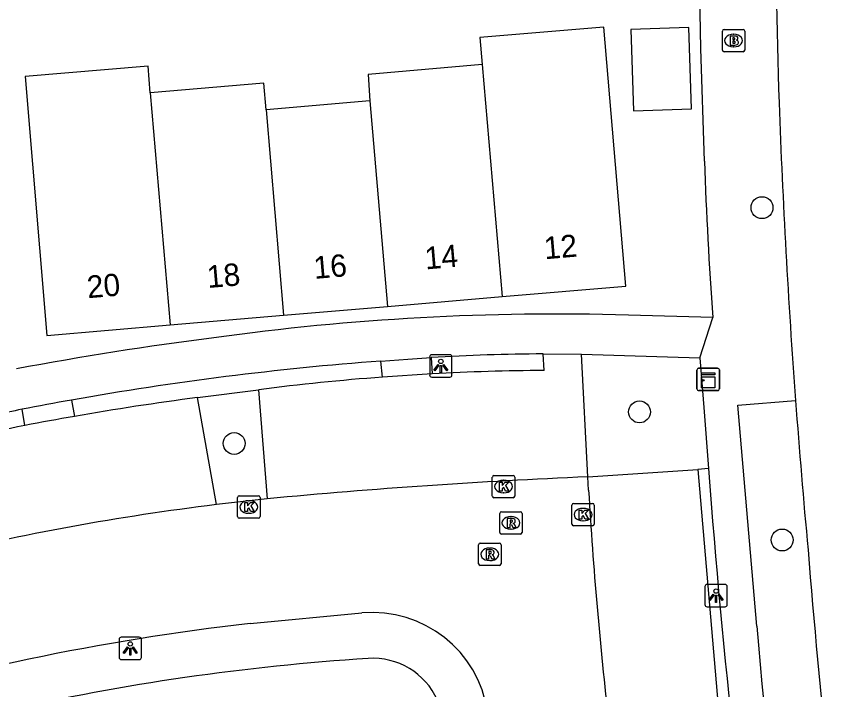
# Model space of a CAD drawing. Extents: x 160158 to 160921, y 381517 to 382041.
# Drawn here: x 160460.93 to 160497.47, y 381637.81 to 381667.92 of the extents above; entities that cross this region are included whole.
import ezdxf

# ---------------------------------------------------------------- set-up
doc = ezdxf.new("R2010")
doc.units = 0
for name, color, linetype in [('IMGEO_Boom', 7, 'Continuous'), ('IMGEO_Brandkraan', 7, 'Continuous'), ('IMGEO_Fietspad_gesloten', 7, 'Continuous'), ('IMGEO_Groenvoorziening', 7, 'Continuous'), ('IMGEO_Haag', 7, 'Continuous'), ('IMGEO_Kast', 7, 'Continuous'), ('IMGEO_Kolk', 7, 'Continuous'), ('IMGEO_Lichtpunt', 7, 'Continuous'), ('IMGEO_Pand', 7, 'Continuous'), ('IMGEO_Pand_nummerreeks', 7, 'Continuous'), ('IMGEO_Parkeervlak_open', 7, 'Continuous'), ('IMGEO_Rijbaan_lokaal_open', 7, 'Continuous'), ('IMGEO_Rioolput', 7, 'Continuous'), ('IMGEO_Voetpad_open', 7, 'Continuous')]:
    doc.layers.add(name, color=color, linetype=linetype)

msp = doc.modelspace()

# ---------------------------------------------------------------- linework, layer by layer
at = {"layer": 'IMGEO_Boom'}
for centre in [(160494.263, 381659.367), (160488.788, 381650.234), (160470.666, 381648.826), (160495.165, 381644.507)]:
    msp.add_circle(centre, 0.489, dxfattribs=at)
at = {"layer": 'IMGEO_Brandkraan'}
for p, q in [((160492.566, 381667.339), (160493.418, 381667.339)), ((160492.491, 381666.413), (160492.491, 381667.265)), ((160492.979, 381667.119), (160493.004, 381667.119)), ((160493.492, 381667.265), (160493.492, 381666.413)), ((160493.418, 381666.339), (160492.566, 381666.339)), ((160493.002, 381666.559), (160492.977, 381666.559))]:
    msp.add_line(p, q, dxfattribs=at)
for points in [[(160492.566, 381667.339), (160493.418, 381667.339)], [(160492.491, 381666.413), (160492.491, 381667.265)], [(160492.839, 381667.039), (160492.839, 381666.639), (160493.052, 381666.639)], [(160493.07, 381667.039), (160492.839, 381667.039)], [(160493.018, 381666.958), (160492.964, 381666.958), (160492.964, 381666.882)], [(160493.492, 381667.265), (160493.492, 381666.413)], [(160492.964, 381666.882), (160493.017, 381666.882)], [(160493.026, 381666.806), (160492.964, 381666.806), (160492.964, 381666.725)], [(160492.964, 381666.725), (160493.026, 381666.725)], [(160493.418, 381666.339), (160492.566, 381666.339)]]:
    msp.add_lwpolyline(points, dxfattribs=at)
for centre, radius, start, end in [((160492.568, 381667.263), 0.0765, 91.552, 178.448), ((160492.568, 381667.263), 0.0765, 91.552, 178.448), ((160493.416, 381667.263), 0.0765, 1.552, 88.448), ((160493.416, 381667.263), 0.0765, 1.552, 88.448), ((160493.019, 381666.92), 0.0379, 267.8285, 90.9355), ((160493.074, 381666.894), 0.145, 59.4692, 91.5367), ((160493.099, 381666.941), 0.0922, 285.5137, 58.1501), ((160493.027, 381666.765), 0.0404, 269.8759, 90.5077), ((160493.058, 381666.89), 0.251, 268.6676, 293.5347), ((160493.104, 381666.749), 0.105, 301.3115, 78.989), ((160492.568, 381666.415), 0.0765, 181.552, 268.448), ((160492.568, 381666.415), 0.0765, 181.552, 268.448), ((160493.416, 381666.415), 0.0765, 271.552, 358.448), ((160493.416, 381666.415), 0.0765, 271.552, 358.448)]:
    msp.add_arc(centre, radius, start, end, dxfattribs=at)
for centre, major_axis, ratio, start_param, end_param in [((160492.978, 381666.839), (-0.387, 0.002), 0.722429, 4.712389, 7.853982), ((160493.003, 381666.839), (-0.39, 0.002), 0.717154, 1.570796, 4.712389)]:
    msp.add_ellipse(centre, major_axis=major_axis, ratio=ratio, start_param=start_param, end_param=end_param, dxfattribs=at)
at = {"layer": 'IMGEO_Fietspad_gesloten'}
for centre, radius, start, end in [((160961.225, 381678.785), 466.43, 179.32125, 181.81004), ((160848.429, 381676.959), 353.637, 182.09162, 184.25039), ((160844.842, 381676.565), 350.03, 184.22954, 185.32615), ((160833.391, 381670.807), 338.126, 184.53487, 187.87102)]:
    msp.add_arc(centre, radius, start, end, dxfattribs=at)
at = {"layer": 'IMGEO_Groenvoorziening'}
msp.add_lwpolyline([(160491.866, 381647.705), (160491.401, 381647.664)], dxfattribs=at)
at = {"layer": 'IMGEO_Haag'}
msp.add_lwpolyline([(160469.024, 381650.876), (160471.76, 381651.227)], dxfattribs=at)
at = {"layer": 'IMGEO_Kast'}
for p, q in [((160491.357, 381651.26), (160491.357, 381652.101)), ((160491.357, 381652.101), (160491.357, 381651.26)), ((160491.432, 381652.185), (160492.273, 381652.185)), ((160492.273, 381652.185), (160491.432, 381652.185)), ((160492.357, 381652.11), (160492.357, 381651.269)), ((160492.357, 381651.269), (160492.357, 381652.11)), ((160492.282, 381651.185), (160491.441, 381651.185)), ((160491.441, 381651.185), (160492.282, 381651.185))]:
    msp.add_line(p, q, dxfattribs=at)
for points in [[(160491.552, 381651.975), (160492.152, 381651.975), (160492.152, 381651.89), (160491.552, 381651.89), (160491.552, 381651.975)], [(160491.552, 381651.8), (160492.152, 381651.8), (160492.152, 381651.311), (160491.552, 381651.311), (160491.552, 381651.8)]]:
    msp.add_lwpolyline(points, dxfattribs=at)
msp.add_circle((160491.636, 381651.649), 0.0377, dxfattribs=at)
for centre, start, end in [((160491.435, 381652.107), 92.4484, 184.2845), ((160491.435, 381652.107), 92.4484, 184.2845), ((160492.279, 381652.107), 2.4484, 94.2845), ((160492.279, 381652.107), 2.4484, 94.2845), ((160491.435, 381651.263), 182.4484, 274.2845), ((160491.435, 381651.263), 182.4484, 274.2845), ((160492.279, 381651.263), 272.4484, 4.2845), ((160492.279, 381651.263), 272.4484, 4.2845)]:
    msp.add_arc(centre, 0.0779, start, end, dxfattribs=at)
at = {"layer": 'IMGEO_Kolk'}
for p, q in [((160482.207, 381646.47), (160482.207, 381647.322)), ((160482.282, 381647.396), (160483.134, 381647.396)), ((160483.208, 381647.322), (160483.208, 381646.47)), ((160482.695, 381647.176), (160482.72, 381647.176)), ((160470.894, 381646.482), (160471.746, 381646.482)), ((160482.718, 381646.616), (160482.693, 381646.616)), ((160470.819, 381645.556), (160470.819, 381646.408)), ((160471.307, 381646.262), (160471.332, 381646.262)), ((160471.82, 381646.408), (160471.82, 381645.556)), ((160483.134, 381646.396), (160482.282, 381646.396)), ((160485.839, 381646.143), (160486.691, 381646.143)), ((160485.764, 381645.217), (160485.764, 381646.069)), ((160486.252, 381645.923), (160486.277, 381645.923)), ((160486.765, 381646.069), (160486.765, 381645.217)), ((160471.746, 381645.482), (160470.894, 381645.482)), ((160471.33, 381645.702), (160471.305, 381645.702)), ((160486.691, 381645.143), (160485.839, 381645.143)), ((160486.275, 381645.363), (160486.25, 381645.363))]:
    msp.add_line(p, q, dxfattribs=at)
for points in [[(160482.207, 381646.47), (160482.207, 381647.322)], [(160482.282, 381647.396), (160483.134, 381647.396)], [(160483.208, 381647.322), (160483.208, 381646.47)], [(160482.528, 381647.096), (160482.651, 381647.096), (160482.651, 381646.945), (160482.781, 381647.096), (160482.945, 381647.096), (160482.799, 381646.945), (160482.952, 381646.696), (160482.8, 381646.696), (160482.715, 381646.86), (160482.651, 381646.793), (160482.651, 381646.696), (160482.528, 381646.696), (160482.528, 381647.096)], [(160470.894, 381646.482), (160471.746, 381646.482)], [(160470.819, 381645.556), (160470.819, 381646.408)], [(160471.14, 381646.182), (160471.263, 381646.182), (160471.263, 381646.031), (160471.393, 381646.182), (160471.557, 381646.182), (160471.411, 381646.031), (160471.564, 381645.782), (160471.412, 381645.782), (160471.327, 381645.946), (160471.263, 381645.879), (160471.263, 381645.782), (160471.14, 381645.782), (160471.14, 381646.182)], [(160471.82, 381646.408), (160471.82, 381645.556)], [(160483.134, 381646.396), (160482.282, 381646.396)], [(160485.839, 381646.143), (160486.691, 381646.143)], [(160485.764, 381645.217), (160485.764, 381646.069)], [(160486.085, 381645.843), (160486.208, 381645.843), (160486.208, 381645.692), (160486.338, 381645.843), (160486.502, 381645.843), (160486.356, 381645.692), (160486.509, 381645.443), (160486.357, 381645.443), (160486.272, 381645.607), (160486.208, 381645.54), (160486.208, 381645.443), (160486.085, 381645.443), (160486.085, 381645.843)], [(160486.765, 381646.069), (160486.765, 381645.217)], [(160471.746, 381645.482), (160470.894, 381645.482)], [(160486.691, 381645.143), (160485.839, 381645.143)]]:
    msp.add_lwpolyline(points, dxfattribs=at)
for centre, start, end in [((160482.284, 381647.32), 91.552, 178.448), ((160482.284, 381647.32), 91.552, 178.448), ((160483.132, 381647.32), 1.552, 88.448), ((160483.132, 381647.32), 1.552, 88.448), ((160470.896, 381646.406), 91.552, 178.448), ((160470.896, 381646.406), 91.552, 178.448), ((160471.744, 381646.406), 1.552, 88.448), ((160471.744, 381646.406), 1.552, 88.448), ((160482.284, 381646.472), 181.552, 268.448), ((160482.284, 381646.472), 181.552, 268.448), ((160483.132, 381646.472), 271.552, 358.448), ((160483.132, 381646.472), 271.552, 358.448), ((160485.841, 381646.067), 91.552, 178.448), ((160485.841, 381646.067), 91.552, 178.448), ((160486.689, 381646.067), 1.552, 88.448), ((160486.689, 381646.067), 1.552, 88.448), ((160470.896, 381645.558), 181.552, 268.448), ((160470.896, 381645.558), 181.552, 268.448), ((160471.744, 381645.558), 271.552, 358.448), ((160471.744, 381645.558), 271.552, 358.448), ((160485.841, 381645.219), 181.552, 268.448), ((160485.841, 381645.219), 181.552, 268.448), ((160486.689, 381645.219), 271.552, 358.448), ((160486.689, 381645.219), 271.552, 358.448)]:
    msp.add_arc(centre, 0.0765, start, end, dxfattribs=at)
for centre, major_axis, ratio, start_param, end_param in [((160482.694, 381646.896), (-0.387, 0.002), 0.722429, 4.712389, 7.853982), ((160482.719, 381646.896), (-0.39, 0.002), 0.717154, 1.570796, 4.712389), ((160471.306, 381645.982), (-0.387, 0.002), 0.722429, 4.712389, 7.853982), ((160471.331, 381645.982), (-0.39, 0.002), 0.717154, 1.570796, 4.712389), ((160486.251, 381645.643), (-0.387, 0.002), 0.722429, 4.712389, 7.853982), ((160486.276, 381645.643), (-0.39, 0.002), 0.717154, 1.570796, 4.712389)]:
    msp.add_ellipse(centre, major_axis=major_axis, ratio=ratio, start_param=start_param, end_param=end_param, dxfattribs=at)
at = {"layer": 'IMGEO_Lichtpunt'}
for p, q in [((160479.406, 381652.695), (160479.406, 381651.888)), ((160479.406, 381652.695), (160479.406, 381651.888)), ((160480.308, 381652.79), (160479.5, 381652.79)), ((160480.308, 381652.79), (160479.5, 381652.79)), ((160480.402, 381651.888), (160480.402, 381652.695)), ((160480.402, 381651.888), (160480.402, 381652.695)), ((160479.5, 381651.794), (160480.308, 381651.794)), ((160479.5, 381651.794), (160480.308, 381651.794)), ((160492.615, 381642.519), (160491.807, 381642.519)), ((160492.615, 381642.519), (160491.807, 381642.519)), ((160491.713, 381642.424), (160491.713, 381641.617)), ((160491.713, 381642.424), (160491.713, 381641.617)), ((160492.709, 381641.617), (160492.709, 381642.424)), ((160492.709, 381641.617), (160492.709, 381642.424)), ((160491.807, 381641.523), (160492.615, 381641.523)), ((160491.807, 381641.523), (160492.615, 381641.523)), ((160465.52, 381640.061), (160465.52, 381639.254)), ((160465.52, 381640.061), (160465.52, 381639.254)), ((160466.422, 381640.156), (160465.614, 381640.156)), ((160466.422, 381640.156), (160465.614, 381640.156)), ((160466.516, 381639.254), (160466.516, 381640.061)), ((160466.516, 381639.254), (160466.516, 381640.061)), ((160465.614, 381639.16), (160466.422, 381639.16)), ((160465.614, 381639.16), (160466.422, 381639.16))]:
    msp.add_line(p, q, dxfattribs=at)
for points in [[(160479.78, 381652.359), (160479.819, 381652.331), (160479.631, 381652.069), (160479.593, 381652.096), (160479.78, 381652.359)], [(160479.992, 381652.331), (160480.03, 381652.358), (160480.217, 381652.096), (160480.178, 381652.068), (160479.992, 381652.331)], [(160479.882, 381652.311), (160479.929, 381652.311), (160479.929, 381651.989), (160479.882, 381651.989), (160479.882, 381652.311)], [(160492.087, 381642.088), (160492.126, 381642.06), (160491.938, 381641.798), (160491.9, 381641.825), (160492.087, 381642.088)], [(160492.189, 381642.04), (160492.236, 381642.04), (160492.236, 381641.718), (160492.189, 381641.718), (160492.189, 381642.04)], [(160492.299, 381642.06), (160492.337, 381642.087), (160492.524, 381641.825), (160492.485, 381641.797), (160492.299, 381642.06)], [(160465.894, 381639.725), (160465.933, 381639.697), (160465.745, 381639.435), (160465.707, 381639.462), (160465.894, 381639.725)], [(160465.996, 381639.677), (160466.043, 381639.677), (160466.043, 381639.355), (160465.996, 381639.355), (160465.996, 381639.677)], [(160466.106, 381639.697), (160466.144, 381639.724), (160466.331, 381639.462), (160466.292, 381639.434), (160466.106, 381639.697)]]:
    msp.add_lwpolyline(points, dxfattribs=at)
for centre in [(160479.905, 381652.493), (160492.212, 381642.222), (160466.019, 381639.859)]:
    msp.add_circle(centre, 0.0994, dxfattribs=at)
for centre, start, end in [((160479.5, 381652.695), 90, 180), ((160479.5, 381652.695), 90, 180), ((160480.308, 381652.695), 0, 90), ((160480.308, 381652.695), 0, 90), ((160479.5, 381651.888), 180, 270), ((160479.5, 381651.888), 180, 270), ((160480.308, 381651.888), 270, 0), ((160480.308, 381651.888), 270, 360), ((160491.807, 381642.424), 90, 180), ((160491.807, 381642.424), 90, 180), ((160492.615, 381642.424), 0, 90), ((160492.615, 381642.424), 0, 90), ((160491.807, 381641.617), 180, 270), ((160491.807, 381641.617), 180, 270), ((160492.615, 381641.617), 270, 0), ((160492.615, 381641.617), 270, 360), ((160465.614, 381640.061), 90, 180), ((160465.614, 381640.061), 90, 180), ((160466.422, 381640.061), 0, 90), ((160466.422, 381640.061), 0, 90), ((160465.614, 381639.254), 180, 270), ((160465.614, 381639.254), 180, 270), ((160466.422, 381639.254), 270, 0), ((160466.422, 381639.254), 270, 360)]:
    msp.add_arc(centre, 0.0946, start, end, dxfattribs=at)
at = {"layer": 'IMGEO_Pand'}
for points in [[(160482.64, 381655.389), (160488.176, 381655.861), (160487.192, 381667.435), (160481.655, 381666.978), (160481.757, 381665.774)], [(160488.516, 381663.696), (160491.118, 381663.781), (160490.999, 381667.427), (160488.396, 381667.341), (160488.516, 381663.696)], [(160466.916, 381664.505), (160466.815, 381665.701), (160461.315, 381665.237), (160462.295, 381653.655), (160467.799, 381654.124)], [(160481.757, 381665.774), (160476.65, 381665.329), (160476.737, 381664.143)], [(160481.757, 381665.774), (160482.64, 381655.389)], [(160472.089, 381663.737), (160471.988, 381664.933), (160466.916, 381664.505)], [(160466.916, 381664.505), (160467.799, 381654.124)], [(160476.737, 381664.143), (160472.089, 381663.737)], [(160476.737, 381664.143), (160477.518, 381654.953)], [(160472.089, 381663.737), (160472.87, 381654.556)], [(160477.518, 381654.953), (160482.64, 381655.389)], [(160472.87, 381654.556), (160477.518, 381654.953)], [(160467.799, 381654.124), (160472.87, 381654.556)]]:
    msp.add_lwpolyline(points, dxfattribs=at)
at = {"layer": 'IMGEO_Parkeervlak_open'}
for points in [[(160484.523, 381652.089), (160484.473, 381652.83)], [(160486.472, 381647.33), (160486.196, 381652.822)], [(160471.76, 381651.227), (160472.144, 381646.347)], [(160469.868, 381646.09), (160469.024, 381650.876)], [(160486.472, 381647.33), (160491.401, 381647.664)], [(160491.401, 381647.664), (160492.337, 381636.731), (160487.421, 381636.32)]]:
    msp.add_lwpolyline(points, dxfattribs=at)
for centre, radius, start, end in [((160485.306, 381546.104), 105.988, 90.42336, 93.12784), ((160485.187, 381546.729), 105.357, 94.29628, 97.32169), ((160485.585, 381524.234), 127.72, 97.45042, 99.94801), ((160485.7, 381524.475), 127.506, 101.02818, 103.41045)]:
    msp.add_arc(centre, radius, start, end, dxfattribs=at)
at = {"layer": 'IMGEO_Rijbaan_lokaal_open'}
for points in [[(160486.513, 381646.739), (160486.472, 381647.33)], [(160472.144, 381646.347), (160469.868, 381646.09)], [(160471.384, 381640.778), (160476.377, 381641.25)]]:
    msp.add_lwpolyline(points, dxfattribs=at)
for centre, radius, start, end in [((160497.989, 381374.552), 273.021, 92.4176, 95.43187), ((160663.736, 381656.935), 177.516, 183.2926, 186.66871), ((160483.62, 381534.543), 112.392, 97.02826, 103.72125), ((160476.833, 381636.056), 5.214, 8.4116, 95.022), ((160484.112, 381530.506), 111.004, 96.58427, 106.94484)]:
    msp.add_arc(centre, radius, start, end, dxfattribs=at)
at = {"layer": 'IMGEO_Rioolput'}
for p, q in [((160482.613, 381645.772), (160483.465, 381645.772)), ((160482.538, 381644.846), (160482.538, 381645.698)), ((160483.026, 381645.552), (160483.051, 381645.552)), ((160483.539, 381645.698), (160483.539, 381644.846)), ((160483.465, 381644.772), (160482.613, 381644.772)), ((160483.049, 381644.992), (160483.024, 381644.992)), ((160481.594, 381643.442), (160481.594, 381644.294)), ((160481.669, 381644.368), (160482.521, 381644.368)), ((160482.595, 381644.294), (160482.595, 381643.442)), ((160482.082, 381644.148), (160482.107, 381644.148)), ((160482.105, 381643.588), (160482.08, 381643.588)), ((160482.521, 381643.368), (160481.669, 381643.368))]:
    msp.add_line(p, q, dxfattribs=at)
for points in [[(160482.613, 381645.772), (160483.465, 381645.772)], [(160482.538, 381644.846), (160482.538, 381645.698)], [(160483.127, 381645.47), (160482.875, 381645.472), (160482.875, 381645.072)], [(160483.053, 381645.391), (160482.999, 381645.391), (160482.999, 381645.31)], [(160483.539, 381645.698), (160483.539, 381644.846)], [(160482.875, 381645.072), (160482.999, 381645.072), (160482.999, 381645.234), (160483.01, 381645.234)], [(160482.999, 381645.31), (160483.051, 381645.31)], [(160483.057, 381645.205), (160483.128, 381645.072), (160483.268, 381645.072), (160483.203, 381645.198)], [(160483.465, 381644.772), (160482.613, 381644.772)], [(160481.594, 381643.442), (160481.594, 381644.294)], [(160481.669, 381644.368), (160482.521, 381644.368)], [(160482.595, 381644.294), (160482.595, 381643.442)], [(160482.183, 381644.066), (160481.931, 381644.068), (160481.931, 381643.668)], [(160482.109, 381643.987), (160482.055, 381643.987), (160482.055, 381643.906)], [(160481.931, 381643.668), (160482.055, 381643.668), (160482.055, 381643.83), (160482.066, 381643.83)], [(160482.055, 381643.906), (160482.107, 381643.906)], [(160482.113, 381643.801), (160482.184, 381643.668), (160482.324, 381643.668), (160482.259, 381643.794)], [(160482.521, 381643.368), (160481.669, 381643.368)]]:
    msp.add_lwpolyline(points, dxfattribs=at)
for centre, radius, start, end in [((160482.615, 381645.696), 0.0765, 91.552, 178.448), ((160482.615, 381645.696), 0.0765, 91.552, 178.448), ((160483.463, 381645.696), 0.0765, 1.552, 88.448), ((160483.463, 381645.696), 0.0765, 1.552, 88.448), ((160483.059, 381645.295), 0.0964, 77.0061, 93.1865), ((160483.073, 381645.352), 0.0378, 276.6634, 79.6772), ((160483.126, 381645.36), 0.109, 350.3612, 89.416), ((160483.009, 381645.181), 0.0533, 26.0293, 88.6989), ((160483.035, 381645.499), 0.19, 274.7715, 282.9687), ((160483.124, 381645.36), 0.112, 277.5842, 350.9817), ((160483.108, 381645.145), 0.108, 29.5134, 73.7905), ((160482.615, 381644.848), 0.0765, 181.552, 268.448), ((160482.615, 381644.848), 0.0765, 181.552, 268.448), ((160483.463, 381644.848), 0.0765, 271.552, 358.448), ((160483.463, 381644.848), 0.0765, 271.552, 358.448), ((160481.671, 381644.292), 0.0765, 91.552, 178.448), ((160481.671, 381644.292), 0.0765, 91.552, 178.448), ((160482.519, 381644.292), 0.0765, 1.552, 88.448), ((160482.519, 381644.292), 0.0765, 1.552, 88.448), ((160482.115, 381643.891), 0.0964, 77.0061, 93.1865), ((160482.129, 381643.948), 0.0378, 276.6634, 79.6772), ((160482.182, 381643.956), 0.109, 350.3612, 89.416), ((160482.18, 381643.956), 0.112, 277.5842, 350.9817), ((160482.065, 381643.777), 0.0533, 26.0293, 88.6989), ((160482.091, 381644.095), 0.19, 274.7715, 282.9687), ((160482.164, 381643.741), 0.108, 29.5134, 73.7905), ((160481.671, 381643.444), 0.0765, 181.552, 268.448), ((160481.671, 381643.444), 0.0765, 181.552, 268.448), ((160482.519, 381643.444), 0.0765, 271.552, 358.448), ((160482.519, 381643.444), 0.0765, 271.552, 358.448)]:
    msp.add_arc(centre, radius, start, end, dxfattribs=at)
for centre, major_axis, ratio, start_param, end_param in [((160483.025, 381645.272), (-0.387, 0.002), 0.722429, 4.712389, 7.853982), ((160483.05, 381645.272), (-0.39, 0.002), 0.717154, 1.570796, 4.712389), ((160482.081, 381643.868), (-0.387, 0.002), 0.722429, 4.712389, 7.853982), ((160482.106, 381643.868), (-0.39, 0.002), 0.717154, 1.570796, 4.712389)]:
    msp.add_ellipse(centre, major_axis=major_axis, ratio=ratio, start_param=start_param, end_param=end_param, dxfattribs=at)
at = {"layer": 'IMGEO_Voetpad_open'}
for points in [[(160492.728, 381711.927), (160491.694, 381694.13), (160491.463, 381687.593), (160491.376, 381681.789), (160491.439, 381672.439), (160491.457, 381669.708), (160491.512, 381666.491), (160491.686, 381661.452)], [(160492.066, 381654.457), (160488.29, 381654.567)], [(160491.492, 381652.649), (160492.066, 381654.457)], [(160484.473, 381652.83), (160486.196, 381652.822)], [(160486.196, 381652.822), (160491.492, 381652.649)], [(160477.228, 381652.508), (160478.426, 381652.592), (160479.479, 381652.663)], [(160477.294, 381651.79), (160477.228, 381652.508)], [(160479.479, 381652.663), (160479.523, 381651.934)], [(160491.492, 381652.649), (160491.667, 381650.431), (160491.866, 381647.705)], [(160479.523, 381651.934), (160477.294, 381651.79)], [(160463.39, 381650.763), (160463.521, 381650.034)], [(160494.031, 381640.656), (160493.18, 381650.533), (160495.765, 381650.749)], [(160461.309, 381649.626), (160461.183, 381650.35)]]:
    msp.add_lwpolyline(points, dxfattribs=at)
for centre, radius, start, end in [((160679.472, 381668.146), 187.905, 182.04142, 184.1776), ((160485.125, 381542.988), 111.624, 88.37544, 97.91678), ((160488.536, 381505.783), 148.954, 97.24509, 100.68216), ((160484.992, 381562.561), 90.27, 90.32929, 93.50123), ((160487.392, 381516.168), 136.718, 94.26334, 100.11102), ((160487.958, 381513.372), 139.571, 100.13841, 101.06015), ((160483.117, 381537.059), 115.395, 100.95735, 102.21334), ((160484.37, 381530.797), 121.046, 99.91831, 100.98301), ((160879.416, 381677.449), 388.689, 184.38877, 188.09689), ((160792.557, 381665.833), 299.586, 184.82081, 190.09257), ((160483.244, 381536.446), 102.975, 93.6643, 102.83892), ((160476.866, 381636.053), 3.164, 24.2735, 93.6845)]:
    msp.add_arc(centre, radius, start, end, dxfattribs=at)

# ---------------------------------------------------------------- texts
at = {"layer": 'IMGEO_Pand_nummerreeks'}
for s, rotation, p in [('12', 4.8759, (160484.557, 381657.058)), ('14', 4.8644, (160479.226, 381656.604)), ('16', 4.8816, (160474.257, 381656.18)), ('18', 4.8701, (160469.488, 381655.773)), ('20', 4.8701, (160464.122, 381655.316))]:
    msp.add_text(s, height=1, rotation=rotation, dxfattribs=at).set_placement(p)

doc.saveas('drawing.dxf')
